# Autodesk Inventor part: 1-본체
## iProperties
Created: 2015-01
Part Number: 1-본체
Document SubType Name: Modeling
Designer: Administrator
Density: 2.71 g/cm^3
Material: 알루미늄-6061
Mass: 1021.33 g
Surface Area: 1059.79 cm^2
Volume: 376.876 cm^3
Author: Administrator
